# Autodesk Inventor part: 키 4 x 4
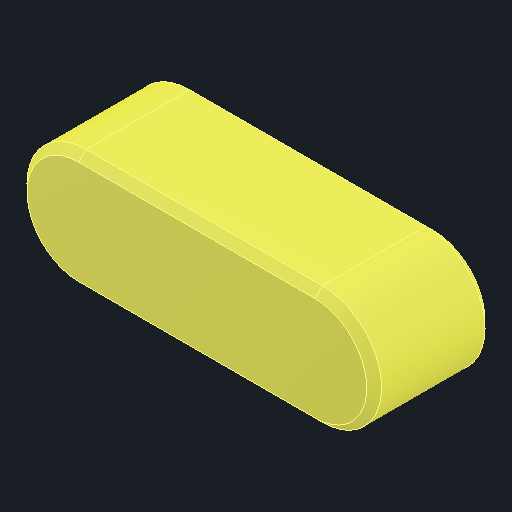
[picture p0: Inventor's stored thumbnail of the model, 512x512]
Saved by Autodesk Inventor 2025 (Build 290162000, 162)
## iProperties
Created: 2025-08
Part Number: 키 4 x 4
Material: 강철, 연강
Description: 키 및 해당 키홈
Document SubType Name: Modeling
Designer: infra17
Density: 7.86 g/cm^3
Appearance: 기본값
Author: jhkim
Sending System: Autodesk Inventor 2026
Preprocessor: ST-DEVELOPER v20.1
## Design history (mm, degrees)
feature "Solid1"
node "솔리드1"
